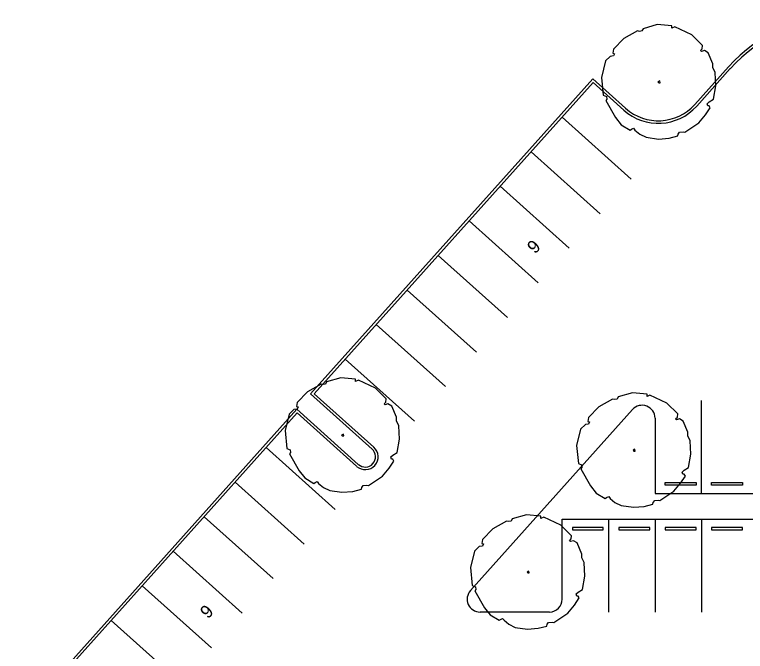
# Model space of a CAD drawing. Extents: x 6712138 to 6712574, y 1869536 to 1870160.
# Drawn here: x 6712228.8 to 6712370.5, y 1870037 to 1870160.5 of the extents above; entities that cross this region are included whole.
import ezdxf

# ---------------------------------------------------------------- set-up
doc = ezdxf.new("R2010")
doc.units = 0
for name, color, linetype in [('A-ANNO-TEXT', 7, 'Continuous'), ('C-PRKG-CONC', 7, 'Continuous'), ('L-tree', 7, 'Continuous')]:
    doc.layers.add(name, color=color, linetype=linetype)

# ---------------------------------------------------------------- blocks, each defined once
blk = doc.blocks.new('TREE 1')
at = {"layer": 'L-tree'}
for p, q in [((-0.2231, 0.5104), (-0.357, 0.4356)), ((-0.2025, 0.506), (-0.2231, 0.5104)), ((-0.1785, 0.5104), (-0.2025, 0.506)), ((-0.1682, 0.5324), (-0.1785, 0.5104)), ((-0.0275, 0.572), (-0.1682, 0.5324)), ((0.1167, 0.5588), (-0.0275, 0.572)), ((0.1167, 0.5368), (0.1167, 0.5588)), ((0.1441, 0.55), (0.1167, 0.5368)), ((0.3123, 0.4708), (0.1441, 0.55)), ((-0.357, 0.4356), (-0.4599, 0.33)), ((0.4187, 0.3652), (0.3123, 0.4708)), ((0.4153, 0.3344), (0.4187, 0.3652)), ((-0.4599, 0.33), (-0.4668, 0.2904)), ((-0.4668, 0.2904), (-0.4496, 0.286)), ((0.3981, 0.3168), (0.4153, 0.3344)), ((0.4084, 0.308), (0.3981, 0.3168)), ((0.4359, 0.3168), (0.4084, 0.308)), ((0.4737, 0.2948), (0.4359, 0.3168)), ((0.5183, 0.1848), (0.4737, 0.2948)), ((-0.4908, 0.2596), (-0.5389, 0.2156)), ((-0.4599, 0.264), (-0.4908, 0.2596)), ((-0.4496, 0.286), (-0.4599, 0.264)), ((-0.5389, 0.2156), (-0.5766, 0.0528)), ((0.5183, 0.1496), (0.5183, 0.1848)), ((0.5423, 0.1012), (0.5183, 0.1496)), ((0.5492, -0.0308), (0.5423, 0.1012)), ((-0.5766, 0.0528), (-0.5595, -0.1232)), ((-0.0034, 0.0176), (-0.0206, 0.0088)), ((-0.0206, 0.0088), (-0.0137, 0)), ((-0.0137, 0), (0, 0)), ((0, 0), (-0.0034, 0.0176)), ((0.5251, -0.1628), (0.5492, -0.0308)), ((-0.5595, -0.1232), (-0.5286, -0.1364)), ((-0.5286, -0.1364), (-0.5251, -0.1628)), ((-0.5251, -0.1628), (-0.5354, -0.176)), ((-0.5354, -0.176), (-0.4393, -0.3432)), ((0.4634, -0.2068), (0.4839, -0.1892)), ((0.4702, -0.2288), (0.4634, -0.2068)), ((0.4839, -0.1892), (0.5251, -0.1628)), ((0.4462, -0.3168), (0.4942, -0.2464)), ((0.4839, -0.2288), (0.4702, -0.2288)), ((0.4942, -0.2464), (0.4839, -0.2288)), ((-0.4393, -0.3432), (-0.3844, -0.4136)), ((0.381, -0.396), (0.4462, -0.3168)), ((-0.3844, -0.4136), (-0.2952, -0.4664)), ((0.2437, -0.4884), (0.381, -0.396)), ((-0.2952, -0.4664), (-0.2815, -0.4576)), ((-0.2815, -0.4576), (-0.2609, -0.4488)), ((-0.2609, -0.4488), (-0.2471, -0.4664)), ((-0.2471, -0.4664), (-0.1991, -0.506)), ((0.1785, -0.506), (0.1922, -0.4884)), ((0.1922, -0.4884), (0.2265, -0.484)), ((0.2265, -0.484), (0.2437, -0.4884)), ((-0.1991, -0.506), (-0.1373, -0.5368)), ((-0.1373, -0.5368), (-0.0172, -0.5544)), ((-0.0172, -0.5544), (0.0892, -0.5456)), ((0.0892, -0.5456), (0.175, -0.5236)), ((0.175, -0.5236), (0.1785, -0.506))]:
    blk.add_line(p, q, dxfattribs=at)

msp = doc.modelspace()

# ---------------------------------------------------------------- linework, layer by layer
at = {"layer": 'C-PRKG-CONC'}
for p, q in [((6712360.69, 1870143.06), (6712367.21, 1870150.33)), ((6712361.07, 1870142.73), (6712367.58, 1870150)), ((6712286.22, 1870086.94), (6712340.95, 1870148)), ((6712347.28, 1870142.33), (6712340.95, 1870148)), ((6712286.92, 1870086.98), (6712340.99, 1870147.3)), ((6712346.95, 1870141.96), (6712340.99, 1870147.3)), ((6712334.98, 1870140.6), (6712348.38, 1870128.58)), ((6712328.97, 1870133.89), (6712342.38, 1870121.88)), ((6712322.97, 1870127.19), (6712336.37, 1870115.18)), ((6712316.96, 1870120.49), (6712330.36, 1870108.48)), ((6712310.95, 1870113.79), (6712324.36, 1870101.77)), ((6712304.95, 1870107.09), (6712318.35, 1870095.07)), ((6712298.94, 1870100.38), (6712312.34, 1870088.37)), ((6712292.93, 1870093.68), (6712306.34, 1870081.67)), ((6712286.22, 1870086.94), (6712298.13, 1870076.26)), ((6712286.92, 1870086.98), (6712298.47, 1870076.63)), ((6712361.99, 1870067.67), (6712361.99, 1870085.67)), ((6712228.82, 1870022.9), (6712283.55, 1870083.96)), ((6712229.52, 1870022.94), (6712283.59, 1870083.26)), ((6712295.46, 1870073.28), (6712283.55, 1870083.96)), ((6712295.13, 1870072.91), (6712283.59, 1870083.26)), ((6712317.2, 1870048.84), (6712348.63, 1870083.91)), ((6712352.99, 1870082.24), (6712352.99, 1870067.67)), ((6712277.58, 1870076.55), (6712290.98, 1870064.54)), ((6712271.57, 1870069.85), (6712284.98, 1870057.84)), ((6712354.96, 1870069.26), (6712354.96, 1870069.76)), ((6712354.96, 1870069.76), (6712360.96, 1870069.76)), ((6712360.96, 1870069.26), (6712354.96, 1870069.26)), ((6712360.96, 1870069.76), (6712360.96, 1870069.26)), ((6712363.96, 1870069.26), (6712363.96, 1870069.76)), ((6712363.96, 1870069.76), (6712369.96, 1870069.76)), ((6712369.96, 1870069.26), (6712363.96, 1870069.26)), ((6712369.96, 1870069.76), (6712369.96, 1870069.26)), ((6712352.99, 1870067.67), (6712397.99, 1870067.67)), ((6712265.57, 1870063.15), (6712278.97, 1870051.14)), ((6712334.99, 1870062.67), (6712397.99, 1870062.67)), ((6712334.99, 1870047.17), (6712334.99, 1870062.67)), ((6712334.99, 1870047.17), (6712334.99, 1870062.67)), ((6712343.99, 1870062.67), (6712343.99, 1870044.67)), ((6712352.99, 1870062.67), (6712352.99, 1870044.67)), ((6712361.99, 1870062.67), (6712361.99, 1870044.67)), ((6712361.99, 1870062.67), (6712361.99, 1870044.67)), ((6712336.96, 1870061.08), (6712336.96, 1870060.58)), ((6712342.96, 1870061.08), (6712336.96, 1870061.08)), ((6712336.96, 1870060.58), (6712342.96, 1870060.58)), ((6712342.96, 1870060.58), (6712342.96, 1870061.08)), ((6712345.96, 1870061.08), (6712345.96, 1870060.58)), ((6712351.96, 1870061.08), (6712345.96, 1870061.08)), ((6712345.96, 1870060.58), (6712351.96, 1870060.58)), ((6712351.96, 1870060.58), (6712351.96, 1870061.08)), ((6712354.96, 1870061.08), (6712354.96, 1870060.58)), ((6712360.96, 1870061.08), (6712354.96, 1870061.08)), ((6712354.96, 1870060.58), (6712360.96, 1870060.58)), ((6712360.96, 1870060.58), (6712360.96, 1870061.08)), ((6712363.96, 1870061.08), (6712363.96, 1870060.58)), ((6712369.96, 1870061.08), (6712363.96, 1870061.08)), ((6712363.96, 1870060.58), (6712369.96, 1870060.58)), ((6712369.96, 1870060.58), (6712369.96, 1870061.08)), ((6712259.56, 1870056.45), (6712272.96, 1870044.44)), ((6712253.55, 1870049.75), (6712266.96, 1870037.73)), ((6712332.52, 1870044.67), (6712319.06, 1870044.67)), ((6712247.54, 1870043.05), (6712260.95, 1870031.03))]:
    msp.add_line(p, q, dxfattribs=at)
for centre, radius, start, end in [((6712389.92, 1870129.97), 30.5, 90, 138.1293), ((6712389.92, 1870129.97), 30, 90, 138.1293), ((6712353.62, 1870149.4), 10, 228.1293, 318.1293), ((6712353.62, 1870149.4), 9.5, 228.1293, 318.1293), ((6712350.49, 1870082.24), 2.5, 360, 138.1293), ((6712296.8, 1870074.77), 2.5, 228.1293, 48.1293), ((6712296.8, 1870074.77), 2, 228.1293, 48.1293), ((6712319.06, 1870047.17), 2.5, 138.1293, 270), ((6712332.49, 1870047.17), 2.5, 270.727, 0)]:
    msp.add_arc(centre, radius, start, end, dxfattribs=at)

# ---------------------------------------------------------------- block references
at = {"layer": 'L-tree', "xscale": 19.68503937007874, "yscale": 19.68503937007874}
for p in [(6712353.97, 1870147.27), (6712292.63, 1870078.79), (6712349.14, 1870075.88), (6712328.58, 1870052.25)]:
    msp.add_blockref('TREE 1', p, dxfattribs=at)

# ---------------------------------------------------------------- texts
at = {"layer": 'A-ANNO-TEXT'}
for p in [(6712329.7, 1870113.97), (6712266.29, 1870043.23)]:
    msp.add_text('9', height=2.5, rotation=45.2528, dxfattribs=at).set_placement(p)

doc.saveas('drawing.dxf')
